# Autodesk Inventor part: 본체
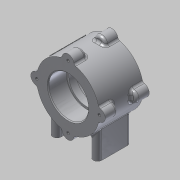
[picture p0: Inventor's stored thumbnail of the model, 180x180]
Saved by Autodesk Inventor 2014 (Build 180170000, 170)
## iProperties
Created: 2015-03
Part Number: 본체
Material: 알루미늄 6061
Document SubType Name: Modeling
Designer: MYHOME
Density: 2.71 g/cm^3
Appearance: 알루미늄 - 평지
Mass: 450.775 g
Surface Area: 332.736 cm^2
Volume: 166.338 cm^3
Author: MYHOME
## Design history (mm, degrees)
sketch "스케치2"
  geometry: C1 r 37 at (0, 0); 1 further point
  constraints: 1 centre point, 1 coincident
  dimensions: "d0" = 74 diameter of C1
extrude "돌출1" new body sketch "스케치2" stored distance "d1" = 52; taper "d2" = 0 deg
node "작업 평면1"
sketch "스케치3"
  geometry: L1 (-24, 15)-(-24, -15); L2 (-19, 15)-(-19, -15); L3 (-29, -15)-(-29, 15); L4 (24, 15)-(24, -15); L5 (29, 15)-(29, -15); L6 (19, -15)-(19, 15); A1 r 5 centre (-24, 15) between (-19, 15) and (-29, 15); A2 r 5 centre (-24, -15) between (-29, -15) and (-19, -15); A3 r 5 centre (24, 15) between (29, 15) and (19, 15); A4 r 5 centre (24, -15) between (19, -15) and (29, -15); 3 further points
  constraints: 16 end point, 8 point on circle, 8 tangent, 4 centre point, 3 parallel, 2 horizontal alignment, 2 midpoint, 1 vertical
  dimensions: "d4" = 10 distance between parallel lines of L3 L2; "d5" = 10 distance between parallel lines of L5 L6; "d6" = 48 distance of point (24, 0) point (-24, 0); "d7" = 40 dimension on A4 A3; "d8" = 40 dimension on A2 A1; "d9" = 24 distance of point (0, 0) point (-24, 0)
extrude "돌출2" join sketch "스케치3" stored distance "d10" = 52; taper "d11" = 0 deg
sketch "스케치4"
  geometry: C1 r 7 at (0, 37); C2 r 7 at (-37, 0); C3 r 7 at (0, -37); C4 r 7 at (37, 0); A1 r 37 centre (0, 0) between (0, 37) and (37, 0) reference
  constraints: 4 centre point, 4 point on circle, 2 horizontal alignment, 2 vertical alignment
  dimensions: "d12" = 14 diameter of C1; "d13" = 14 diameter of C4; "d14" = 14 diameter of C3; "d15" = 14 diameter of C2
extrude "돌출3" join sketch "스케치4" distance "d16" = 15; taper "d17" = 0 deg
sketch "스케치5"
  geometry: A1 r 7 centre (0, 37) between (6.969, 36.338) and (-6.969, 36.338) reference; A2 r 7 centre (-37, 0) between (-36.338, 6.969) and (-36.338, -6.969) reference; A3 r 7 centre (0, -37) between (-6.969, -36.338) and (6.969, -36.338) reference; A4 r 7 centre (37, 0) between (36.338, -6.969) and (36.338, 6.969) reference; 4 further points
  constraints: 4 coincident
hole "구멍1" sketch "스케치5" at (37, 0), (0, 37), (-37, 0), (0, -37) diameter "d18" = 3.242; stored, may be unused: countersink angle "d22" = 90 deg, drill point angle "d24" = 118 deg; dims "d19" = 8, "d20" = 4, "d21" = 2, "d23" = 11
hole "구멍2" diameter "d27" = 42; stored, may be unused: countersink angle "d31" = 90 deg, drill point angle "d33" = 0 deg; dims "d25" = 10, "d26" = 10, "d28" = 8, "d29" = 47, "d30" = 22, "d32" = 30
sketch "스케치6"
  geometry: C1 r 23.5 at (0, 0); A1 r 37 centre (0, 0) between (6.969, -36.338) and (36.338, -6.969) reference
  constraints: 1 centre point, 1 coincident
  dimensions: "d34" = 47 diameter of C1
extrude "돌출4" cut sketch "스케치6" distance "d35" = 22; taper "d36" = 0 deg
sketch "스케치7"
  geometry: L1 (19, 15)-(19, -15) reference; L2 (29, -15)-(29, 15) reference; A1 r 5 centre (-24, -15) between (-29, -15) and (-19, -15) reference; A2 r 5 centre (-24, 15) between (-19, 15) and (-29, 15) reference; A3 r 5 centre (24, -15) between (19, -15) and (29, -15) reference; A4 r 5 centre (24, 15) between (29, 15) and (19, 15) reference; 5 further points
  constraints: 4 coincident
hole "구멍3" sketch "스케치7" at (-24, 15), (-24, -15), (24, 15), (24, -15) diameter "d37" = 4.134; stored, may be unused: countersink angle "d41" = 90 deg, drill point angle "d43" = 118 deg; dims "d38" = 6, "d39" = 47, "d40" = 22, "d42" = 8
fillet "모깎기1" dims "d44" = 3
fillet "모깎기2" dims "d45" = 3
fillet "모깎기3" dims "d46" = 0.3
chamfer "모따기1" distance "d47" = 1; stored, may be unused: second distance "d48" = 2, angle "d49" = 45 deg
sketch "스케치8"
  geometry: L1 (21, 0)-(0, 0); L2 (0, 0)-(26.163, 26.163); A1 r 37 centre (0, 0) between (35.862, 9.104) and (9.104, 35.862) reference; 2 further points
  constraints: 4 end point, 1 horizontal, 1 horizontal alignment, 1 point on circle, 1 other
  dimensions: "d50" = 45 deg angle of L2 L1
node "작업 평면2"
sketch "스케치10"
  geometry: 2 further points
  constraints: 1 coincident, 1 other
feature "엠보싱2" sketch "스케치10" dims "d53" = 0.5, "d54" = 0
fillet "모깎기4" dims "d55" = 3
node "솔리드1"
mirror "대칭1"
node "투영된 루프1"
other parameters: "d3" = -56
